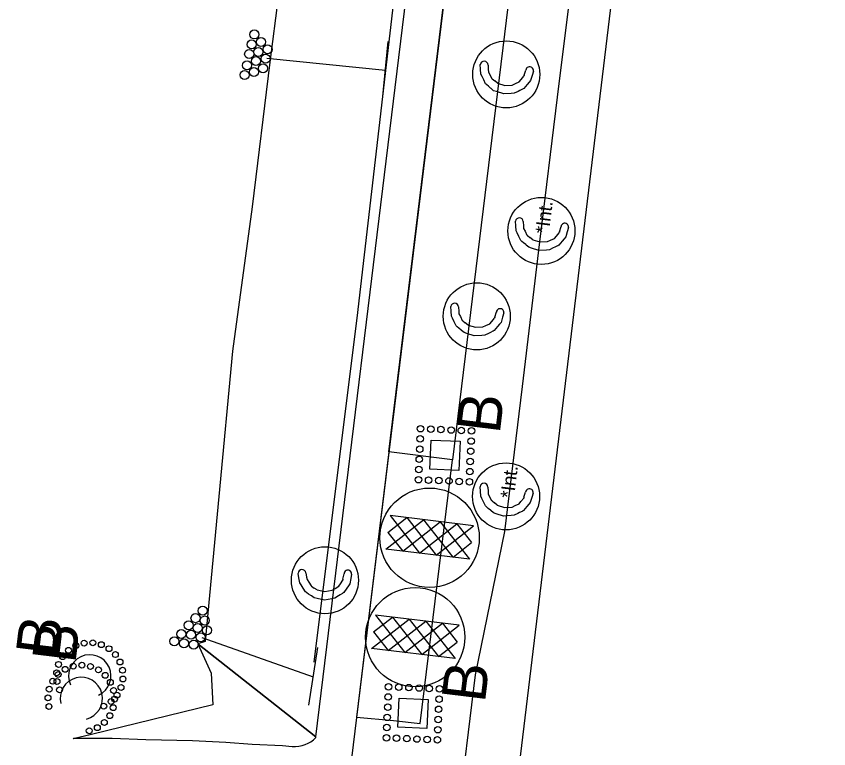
# Model space of a CAD drawing. Extents: x 400935 to 481562, y 415700 to 505362.
# Drawn here: x 481115.8 to 481394.6, y 490263.4 to 490514.5 of the extents above; entities that cross this region are included whole.
import ezdxf

# ---------------------------------------------------------------- set-up
doc = ezdxf.new("R2010")
doc.units = 0
for name, color, linetype in [('Coir Fiber Wattle with PAM Final CELL', 7, 'Continuous'), ('Drain Terminator Final CELL', 7, 'Continuous'), ('Earth Berm for Slope Drains Final', 7, 'Continuous'), ('Label B CG CELL', 7, 'Continuous'), ('Label B Final CELL', 7, 'Continuous'), ('Matting on Slope Note Final CELL', 7, 'Continuous'), ('Old_Level_2', 7, 'Continuous'), ('Rock Inlet Sediment Trap Type B Final CELL', 7, 'Continuous'), ('Rock Pipe Inlet Sediment Trap Type B CG CELL', 7, 'Continuous'), ('Rock Pipe Inlet Sediment Trap Type B Final CELL', 7, 'Continuous'), ('Rock Silt Check Type A with Matting and PAM Final CELL', 7, 'Continuous'), ('Scratch_Level_3', 7, 'Continuous'), ('Scratch_Level_4', 7, 'Continuous'), ('Slope Drain Final', 7, 'Continuous'), ('Slope Drain Inlet Final CELL', 7, 'Continuous')]:
    doc.layers.add(name, color=color, linetype=linetype)

msp = doc.modelspace()

# ---------------------------------------------------------------- linework, layer by layer
at = {"layer": 'Coir Fiber Wattle with PAM Final CELL'}
for p, q in [((481277.7, 490497.83), (481277.79, 490496.28)), ((481277.79, 490496.28), (481277.83, 490495.49)), ((481277.83, 490495.49), (481278.33, 490494.5)), ((481278.33, 490494.5), (481278.97, 490493.2)), ((481289.08, 490492.86), (481290.02, 490494)), ((481290.12, 490494.32), (481290.02, 490494)), ((481290.12, 490494.32), (481290.69, 490496.09)), ((481279.16, 490493.05), (481278.97, 490493.2)), ((481279.16, 490493.05), (481280.02, 490492.35)), ((481280.95, 490491.61), (481280.02, 490492.35)), ((481280.95, 490491.61), (481283.47, 490490.84)), ((481283.48, 490490.84), (481283.47, 490490.84)), ((481283.48, 490490.84), (481286.02, 490490.96)), ((481286.02, 490490.96), (481287.11, 490491.46)), ((481287.11, 490491.46), (481288.42, 490492.07)), ((481288.42, 490492.07), (481289.08, 490492.86)), ((481267.58, 490414.87), (481267.66, 490413.32)), ((481267.66, 490413.32), (481267.71, 490412.53)), ((481267.71, 490412.53), (481268.2, 490411.54)), ((481280, 490411.36), (481280.57, 490413.13)), ((481268.2, 490411.54), (481268.85, 490410.24)), ((481269.03, 490410.09), (481268.85, 490410.24)), ((481269.03, 490410.09), (481269.9, 490409.39)), ((481278.29, 490409.11), (481278.95, 490409.9)), ((481278.95, 490409.9), (481279.9, 490411.04)), ((481280, 490411.36), (481279.9, 490411.04)), ((481270.83, 490408.65), (481269.9, 490409.39)), ((481270.83, 490408.65), (481273.34, 490407.88)), ((481273.35, 490407.88), (481273.34, 490407.88)), ((481273.35, 490407.88), (481275.89, 490408)), ((481275.89, 490408), (481276.98, 490408.5)), ((481276.98, 490408.5), (481278.29, 490409.11)), ((481215.19, 490323.67), (481215.44, 490322.14)), ((481227.91, 490321.49), (481228.29, 490323.32)), ((481215.44, 490322.14), (481215.57, 490321.36)), ((481215.57, 490321.36), (481216.16, 490320.43)), ((481227.02, 490319.94), (481227.84, 490321.17)), ((481227.91, 490321.49), (481227.84, 490321.17)), ((481216.16, 490320.43), (481216.94, 490319.21)), ((481217.14, 490319.08), (481216.94, 490319.21)), ((481217.14, 490319.08), (481218.07, 490318.48)), ((481219.07, 490317.83), (481218.07, 490318.48)), ((481219.07, 490317.83), (481221.66, 490317.33)), ((481221.67, 490317.33), (481224.18, 490317.72)), ((481224.18, 490317.72), (481225.21, 490318.34)), ((481225.21, 490318.34), (481226.45, 490319.08)), ((481226.45, 490319.08), (481227.02, 490319.94)), ((481221.67, 490317.33), (481221.66, 490317.33))]:
    msp.add_line(p, q, dxfattribs=at)
for points in [[(481293.27, 490495.77), (481292.82, 490494.28), (481292.29, 490492.54), (481291.76, 490491.9), (481291.11, 490491.12), (481289.97, 490489.74), (481289.93, 490489.72), (481289.54, 490489.52), (481289.47, 490489.49), (481288.61, 490489.07), (481288.02, 490488.77), (481286.7, 490488.13), (481285.66, 490488.05), (481283.12, 490487.89), (481283.11, 490487.89), (481280.59, 490488.69), (481279.61, 490489.01), (481278.75, 490489.74), (481278.57, 490489.9), (481277.84, 490490.52), (481277.29, 490490.99), (481277.16, 490491.11), (481276.88, 490491.35), (481276.87, 490491.35), (481276.21, 490492.71), (481275.63, 490493.92), (481275.28, 490494.65), (481275.15, 490496.4), (481275.04, 490497.95)], [(481283.14, 490412.81), (481282.69, 490411.32), (481282.16, 490409.58), (481281.63, 490408.94), (481280.99, 490408.16), (481279.85, 490406.77), (481279.81, 490406.76), (481279.41, 490406.56), (481279.35, 490406.53), (481278.49, 490406.1), (481277.89, 490405.81), (481276.58, 490405.16), (481275.54, 490405.09), (481272.99, 490404.93), (481272.98, 490404.93), (481270.47, 490405.73), (481269.49, 490406.05), (481268.63, 490406.78), (481268.45, 490406.94), (481267.72, 490407.56), (481267.16, 490408.03), (481267.03, 490408.15), (481266.75, 490408.38), (481266.75, 490408.39), (481266.09, 490409.75), (481265.5, 490410.96), (481265.15, 490411.69), (481265.03, 490413.44), (481264.92, 490414.98)], [(481230.88, 490323.28), (481230.59, 490321.74), (481230.25, 490319.96), (481229.79, 490319.26), (481229.23, 490318.42), (481228.24, 490316.92), (481228.21, 490316.9), (481227.84, 490316.66), (481227.77, 490316.62), (481226.96, 490316.11), (481226.4, 490315.76), (481225.16, 490314.98), (481224.14, 490314.8), (481221.62, 490314.36), (481221.61, 490314.36), (481219.03, 490314.9), (481218.02, 490315.11), (481217.09, 490315.75), (481216.89, 490315.88), (481216.1, 490316.42), (481215.5, 490316.84), (481215.36, 490316.93), (481215.05, 490317.14), (481215.05, 490317.15), (481214.25, 490318.43), (481213.54, 490319.57), (481213.11, 490320.26), (481212.8, 490321.99), (481212.53, 490323.51)]]:
    msp.add_lwpolyline(points, dxfattribs=at)
for centre in [(481283.95, 490494.61), (481273.83, 490411.65), (481221.74, 490321.13)]:
    msp.add_circle(centre, 11.5, dxfattribs=at)
for centre, radius, start, end in [((481276.37, 490497.78), 1.33, 1.9296, 173.0423), ((481291.98, 490495.93), 1.3, 353.0423, 173.0423), ((481266.24, 490414.82), 1.33, 1.9296, 173.0423), ((481281.85, 490412.97), 1.3, 353.0423, 173.0423), ((481213.87, 490323.49), 1.33, 7.986, 179.0986), ((481229.59, 490323.3), 1.3, 359.0986, 179.0986)]:
    msp.add_arc(centre, radius, start, end, dxfattribs=at)
at = {"layer": 'Drain Terminator Final CELL'}
for centre in [(481197.46, 490508.3), (481196.57, 490504.88), (481199.75, 490505.74), (481202.03, 490503.18), (481195.72, 490501.59), (481198.85, 490502.32), (481194.99, 490497.71), (481198.03, 490499.17), (481201.34, 490499.99), (481197.34, 490495.42), (481200.48, 490496.7), (481194.13, 490494.43), (481179.75, 490310.68), (481177.3, 490308.14), (481174.94, 490305.69), (481180.48, 490307.33), (481172.4, 490302.67), (481175.77, 490302.44), (481178.03, 490304.79), (481181.22, 490303.98), (481170.04, 490300.22), (481173.32, 490299.51), (481179.05, 490301.54), (481176.69, 490299.09)]:
    msp.add_circle(centre, 1.55, dxfattribs=at)
at = {"layer": 'Earth Berm for Slope Drains Final'}
msp.add_lwpolyline([(481271.37, 490730.91), (481254.01, 490595.72), (481232.68, 490411.03), (481219.82, 490308.67), (481217.86, 490293.05)], dxfattribs=at)
at = {"layer": 'Matting on Slope Note Final CELL'}
for p, q in [((481218.64, 490267.48), (481278.21, 490755.15)), ((481209.33, 490548.43), (481202.79, 490498.86)), ((481202.79, 490498.86), (481196.72, 490449.23)), ((481196.72, 490449.23), (481190.04, 490399.67)), ((481190.04, 490399.67), (481185.35, 490349.87)), ((481185.35, 490349.87), (481180.63, 490300.08)), ((481180.63, 490300.08), (481178.12, 490299.33)), ((481178.12, 490299.33), (481218.64, 490267.48)), ((481218.64, 490267.48), (481178.12, 490299.33)), ((481178.12, 490299.33), (481182.63, 490289.24)), ((481182.63, 490289.24), (481183.29, 490278.39)), ((481183.29, 490278.39), (481141.66, 490268.26)), ((481141.66, 490268.26), (481135.3, 490266.75)), ((481135.49, 490266.95), (481142, 490266.98)), ((481135.49, 490266.95), (481135.49, 490266.95)), ((481142, 490266.98), (481148.67, 490266.96)), ((481176.29, 490266.13), (481187.67, 490265.56)), ((481218.61, 490267.2), (481218.64, 490267.48))]:
    msp.add_line(p, q, dxfattribs=at)
for points in [[(481135.3, 490266.75), (481135.49, 490266.95), (481135.49, 490266.95), (481135.49, 490266.95)], [(481135.49, 490266.95), (481135.49, 490266.95), (481135.49, 490266.95), (481135.3, 490266.75), (481135.49, 490266.95)], [(481148.67, 490266.96), (481160.22, 490266.52), (481176.29, 490266.13)], [(481187.67, 490265.56), (481196.77, 490264.92), (481207.17, 490264.46), (481210.53, 490264.16), (481210.53, 490264.16)]]:
    msp.add_lwpolyline(points, dxfattribs=at)
msp.add_arc((481211.4, 490274.13), 10, 265.0508, 316.1666, dxfattribs=at)
at = {"layer": 'Old_Level_2'}
for p, q in [((481289.77, 490444.15), (481289.85, 490442.6)), ((481289.85, 490442.6), (481289.9, 490441.81)), ((481289.9, 490441.81), (481290.39, 490440.82)), ((481290.39, 490440.82), (481291.04, 490439.52)), ((481302.19, 490440.63), (481302.09, 490440.32)), ((481302.19, 490440.63), (481302.76, 490442.41)), ((481291.22, 490439.37), (481291.04, 490439.52)), ((481291.22, 490439.37), (481292.09, 490438.67)), ((481293.02, 490437.93), (481292.09, 490438.67)), ((481293.02, 490437.93), (481295.53, 490437.16)), ((481298.08, 490437.27), (481299.17, 490437.78)), ((481299.17, 490437.78), (481300.48, 490438.39)), ((481300.48, 490438.39), (481301.14, 490439.18)), ((481301.14, 490439.18), (481302.09, 490440.32)), ((481295.54, 490437.16), (481295.53, 490437.16)), ((481295.54, 490437.16), (481298.08, 490437.27)), ((481277.62, 490353.11), (481277.71, 490351.56)), ((481277.71, 490351.56), (481277.75, 490350.77)), ((481290.04, 490349.6), (481290.61, 490351.37)), ((481277.75, 490350.77), (481278.25, 490349.78)), ((481278.25, 490349.78), (481278.9, 490348.48)), ((481279.08, 490348.33), (481278.9, 490348.48)), ((481289, 490348.14), (481289.94, 490349.28)), ((481290.04, 490349.6), (481289.94, 490349.28)), ((481279.08, 490348.33), (481279.94, 490347.64)), ((481280.87, 490346.89), (481279.94, 490347.64)), ((481280.87, 490346.89), (481283.39, 490346.12)), ((481283.4, 490346.12), (481283.39, 490346.12)), ((481283.4, 490346.12), (481285.94, 490346.24)), ((481285.94, 490346.24), (481287.03, 490346.74)), ((481287.03, 490346.74), (481288.34, 490347.35)), ((481288.34, 490347.35), (481289, 490348.14))]:
    msp.add_line(p, q, dxfattribs=at)
for points in [[(481305.33, 490442.09), (481304.88, 490440.6), (481304.35, 490438.86), (481303.82, 490438.22), (481303.18, 490437.44), (481302.04, 490436.05), (481302, 490436.03), (481301.6, 490435.84), (481301.54, 490435.81), (481300.68, 490435.38), (481300.08, 490435.09), (481298.77, 490434.44), (481297.73, 490434.37), (481295.18, 490434.21), (481295.17, 490434.21), (481292.66, 490435.01), (481291.68, 490435.33), (481290.82, 490436.06), (481290.64, 490436.22), (481289.91, 490436.84), (481289.35, 490437.31), (481289.22, 490437.43), (481288.94, 490437.66), (481288.94, 490437.67), (481288.28, 490439.03), (481287.69, 490440.24), (481287.34, 490440.97), (481287.22, 490442.72), (481287.11, 490444.26)], [(481293.19, 490351.05), (481292.74, 490349.56), (481292.21, 490347.82), (481291.68, 490347.18), (481291.03, 490346.4), (481289.89, 490345.01), (481289.85, 490345), (481289.46, 490344.8), (481289.39, 490344.77), (481288.53, 490344.34), (481287.94, 490344.05), (481286.62, 490343.41), (481285.58, 490343.33), (481283.04, 490343.17), (481283.03, 490343.17), (481280.51, 490343.97), (481279.53, 490344.29), (481278.67, 490345.02), (481278.49, 490345.18), (481277.76, 490345.8), (481277.21, 490346.27), (481277.08, 490346.39), (481276.8, 490346.63), (481276.79, 490346.63), (481276.13, 490347.99), (481275.55, 490349.2), (481275.2, 490349.93), (481275.07, 490351.68), (481274.96, 490353.23)]]:
    msp.add_lwpolyline(points, dxfattribs=at)
for centre in [(481296.02, 490440.93), (481283.87, 490349.89)]:
    msp.add_circle(centre, 11.5, dxfattribs=at)
for centre, radius, start in [((481288.43, 490444.1), 1.33, 1.9239), ((481304.05, 490442.25), 1.3, 353.0365), ((481276.29, 490353.06), 1.33, 1.9239), ((481291.9, 490351.21), 1.3, 353.0365)]:
    msp.add_arc(centre, radius, start, 173.0365, dxfattribs=at)
at = {"layer": 'Rock Inlet Sediment Trap Type B Final CELL'}
for points in [[(481257.73, 490359.21), (481258.15, 490369.2), (481268.14, 490368.78), (481267.71, 490358.79)], [(481246.73, 490270.72), (481247.15, 490280.71), (481257.14, 490280.29), (481256.71, 490270.3)]]:
    msp.add_lwpolyline(points, close=True, dxfattribs=at)
for centre in [(481254.55, 490373.1), (481258.04, 490372.96), (481261.54, 490372.81), (481265.04, 490372.66), (481268.53, 490372.51), (481272.03, 490372.37), (481254.4, 490369.61), (481271.88, 490368.87), (481254.25, 490366.11), (481271.74, 490365.37), (481254.1, 490362.61), (481271.59, 490361.88), (481253.96, 490359.12), (481253.81, 490355.62), (481271.44, 490358.38), (481257.31, 490355.47), (481260.8, 490355.32), (481264.3, 490355.18), (481267.8, 490355.03), (481271.3, 490354.88), (481243.55, 490284.61), (481247.05, 490284.46), (481250.55, 490284.31), (481254.04, 490284.17), (481257.54, 490284.02), (481261.04, 490283.87), (481243.41, 490281.11), (481260.89, 490280.37), (481243.26, 490277.61), (481260.74, 490276.88), (481243.11, 490274.12), (481260.6, 490273.38), (481242.96, 490270.62), (481260.45, 490269.88), (481242.82, 490267.12), (481246.31, 490266.98), (481249.81, 490266.83), (481253.31, 490266.68), (481256.8, 490266.53), (481260.3, 490266.39)]:
    msp.add_circle(centre, 1.12, dxfattribs=at)
at = {"layer": 'Rock Pipe Inlet Sediment Trap Type B CG CELL'}
for centre in [(481135.34, 490291.69), (481138.3, 490292.02), (481141.25, 490291.58), (481130.16, 490288.83), (481132.56, 490290.6), (481143.98, 490290.39), (481128.3, 490286.5), (481146.31, 490288.53), (481148.08, 490286.13), (481127.11, 490283.76), (481149.17, 490283.35), (481126.66, 490280.81), (481127, 490277.85), (481149.51, 490280.39), (481149.06, 490277.44), (481146.01, 490272.38), (481147.87, 490274.71), (481140.84, 490269.51), (481143.61, 490270.6)]:
    msp.add_circle(centre, 1.01, dxfattribs=at)
msp.add_arc((481138.09, 490280.6), 7.26, 283.9393, 193.9305, dxfattribs=at)
at = {"layer": 'Rock Pipe Inlet Sediment Trap Type B Final CELL'}
for centre in [(481136.23, 490298.7), (481139.08, 490299.59), (481142.06, 490299.7), (481144.97, 490299.05), (481147.61, 490297.66), (481131.69, 490294.92), (481133.71, 490297.11), (481149.8, 490295.64), (481130.3, 490292.28), (481151.39, 490293.12), (481129.64, 490289.37), (481152.28, 490290.27), (481129.76, 490286.39), (481152.4, 490287.29), (481130.65, 490283.54), (481151.74, 490284.38), (481150.35, 490281.74), (481145.81, 490277.96), (481148.33, 490279.55)]:
    msp.add_circle(centre, 1.01, dxfattribs=at)
msp.add_arc((481141.02, 490288.33), 7.26, 294.7898, 204.781, dxfattribs=at)
at = {"layer": 'Rock Silt Check Type A with Matting and PAM Final CELL'}
for p, q in [((481244.06, 490343.31), (481254.13, 490330.45)), ((481272.75, 490339.81), (481244.06, 490343.31)), ((481242.66, 490331.85), (481255.53, 490341.91)), ((481243.35, 490337.56), (481249.82, 490342.61)), ((481248.42, 490331.13), (481261.28, 490341.21)), ((481249.82, 490342.61), (481259.88, 490329.75)), ((481254.13, 490330.45), (481267.04, 490340.51)), ((481255.53, 490341.91), (481265.64, 490329.04)), ((481261.28, 490341.21), (481271.35, 490328.35)), ((481267.04, 490340.51), (481272.06, 490334.05)), ((481243.35, 490337.56), (481248.42, 490331.13)), ((481259.88, 490329.75), (481272.75, 490339.81)), ((481271.35, 490328.35), (481242.66, 490331.85)), ((481265.7, 490329.09), (481272.06, 490334.05)), ((481237.72, 490297.76), (481250.58, 490307.82)), ((481238.4, 490303.46), (481244.88, 490308.52)), ((481239.12, 490309.22), (481249.18, 490296.36)), ((481267.81, 490305.72), (481239.12, 490309.22)), ((481243.47, 490297.04), (481256.34, 490307.12)), ((481244.88, 490308.52), (481254.94, 490295.65)), ((481250.58, 490307.82), (481260.7, 490294.95)), ((481256.34, 490307.12), (481266.41, 490294.25)), ((481249.18, 490296.36), (481262.1, 490306.41)), ((481254.94, 490295.65), (481267.81, 490305.72)), ((481262.1, 490306.41), (481267.12, 490299.96)), ((481238.4, 490303.46), (481243.47, 490297.04)), ((481260.75, 490294.99), (481267.12, 490299.96)), ((481266.41, 490294.25), (481237.72, 490297.76))]:
    msp.add_line(p, q, dxfattribs=at)
for centre in [(481257.65, 490335.71), (481252.71, 490301.61)]:
    msp.add_circle(centre, 17.04, dxfattribs=at)
at = {"layer": 'Scratch_Level_3'}
msp.add_lwpolyline([(481267.31, 490239.12), (481273.37, 490288.75), (481283.41, 490337.89), (481289.47, 490387.53), (481295.53, 490437.16), (481301.59, 490486.79), (481307.66, 490536.42), (481313.72, 490586.05), (481319.78, 490635.68), (481344.03, 490834.21), (481350.48, 490883.79), (481356.71, 490933.4), (481362.86, 490983.02), (481368.68, 491032.68), (481374.34, 491082.36), (481382.38, 491131.75), (481382.5, 491182.11), (481388.13, 491231.38), (481392.2, 491280.61), (481394.63, 491329.96)], dxfattribs=at)
at = {"layer": 'Scratch_Level_4'}
for points in [[(481192.51, 489946.27), (481250.03, 489939.44), (481357.88, 490832.14), (481301.55, 490839.02)], [(481243.67, 490365.16), (481301.5, 490838.64), (481323.34, 490835.97), (481265.51, 490362.49)], [(481245.27, 490273.1), (481254.45, 490271.98), (481265.51, 490362.49), (481243.67, 490365.16), (481232.56, 490274.15)]]:
    msp.add_lwpolyline(points, close=True, dxfattribs=at)
at = {"layer": 'Slope Drain Final'}
for p, q in [((481242.49, 490495.89), (481201.83, 490500.09)), ((481217.78, 490287.93), (481179.53, 490301.39))]:
    msp.add_line(p, q, dxfattribs=at)
at = {"layer": 'Slope Drain Inlet Final CELL'}
for p, q in [((481241.5, 490485.94), (481243.47, 490505.84)), ((481216.23, 490278.34), (481219.23, 490298.11))]:
    msp.add_line(p, q, dxfattribs=at)

# ---------------------------------------------------------------- texts
at = {"layer": 'Label B CG CELL'}
msp.add_text('B', height=15, rotation=83.0423, dxfattribs=at).set_placement((481136.06, 490292.34))
at = {"layer": 'Label B Final CELL'}
for rotation, p in [(83.0423, (481281.68, 490371.03)), (83.0365, (481130.47, 490294.55)), (83.0423, (481276.6, 490278.83))]:
    msp.add_text('B', height=15, rotation=rotation, dxfattribs=at).set_placement(p)
at = {"layer": 'Old_Level_2'}
for p in [(481298.57, 490439.75), (481286.6, 490349.04)]:
    msp.add_text('*Int.', height=4.746, rotation=83.0423, dxfattribs=at).set_placement(p)

doc.saveas('drawing.dxf')
